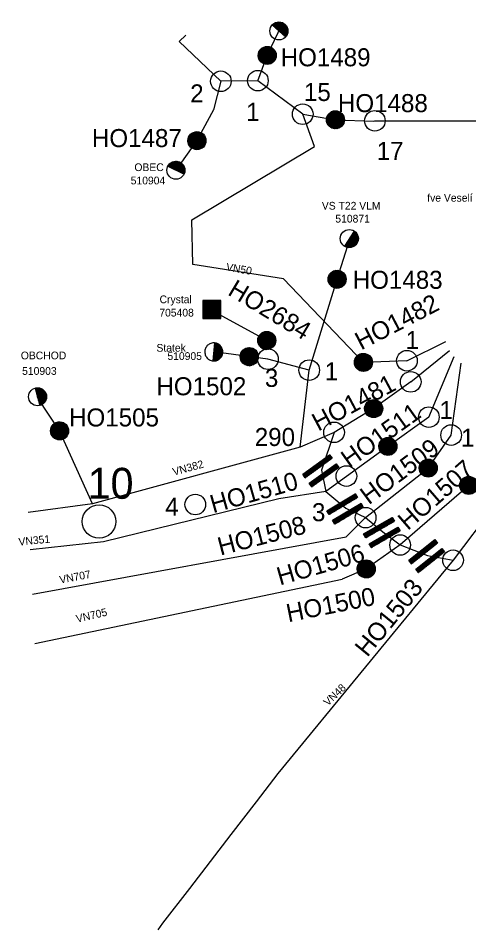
# Model space of a CAD drawing. Extents: x -546092 to -542700, y -1196659 to -1193917.
# Drawn here: x -546092 to -545218, y -1195969 to -1194201 of the extents above; entities that cross this region are included whole.
import ezdxf

# ---------------------------------------------------------------- set-up
doc = ezdxf.new("R2010")
doc.units = 0
for name, color, linetype in [('Default', 7, 'Continuous'), ('Vrstva 1', 7, 'Continuous'), ('Vrstva 2', 7, 'Continuous'), ('Vrstva 3', 7, 'Continuous'), ('Vrstva 5', 7, 'Continuous')]:
    doc.layers.add(name, color=color, linetype=linetype)

# ---------------------------------------------------------------- blocks, each defined once
blk = doc.blocks.new('PS100')
at = {"layer": 'Default'}
for p, q in [((-17.5, -0.7), (0.7, 17.5)), ((-17.5, 0.7), (-0.7, 17.5)), ((-17.4, -2), (2, 17.4)), ((-17.3, 2.2), (-2.2, 17.3)), ((-17.2, -3.3), (3.3, 17.2)), ((-17, 4), (-4, 17)), ((-16.9, -4.4), (4.4, 16.9)), ((-16.6, -5.5), (5.5, 16.6)), ((-16.4, 6), (-6, 16.4)), ((-16.2, -6.5), (6.5, 16.2)), ((-15.8, -7.5), (7.5, 15.8)), ((-15.3, -8.4), (8.4, 15.3)), ((-15.2, 8.6), (-8.6, 15.2)), ((-14.8, -9.3), (9.3, 14.8)), ((-14.2, -10.2), (10.2, 14.2)), ((-13.6, -11), (11, 13.6)), ((-13, -11.7), (11.7, 13)), ((-12.3, -12.5), (12.5, 12.3)), ((-11.5, -13.2), (13.2, 11.5)), ((-10.8, -13.8), (13.8, 10.8)), ((-9.9, -14.4), (14.4, 9.9)), ((-9.1, -14.9), (14.9, 9.1)), ((-8.2, -15.5), (15.5, 8.2)), ((-7.2, -15.9), (15.9, 7.2)), ((-6.2, -16.3), (16.3, 6.2)), ((-5.2, -16.7), (16.7, 5.2)), ((-4.1, -17), (17, 4.1)), ((-2.9, -17.2), (17.2, 2.9)), ((-1.6, -17.4), (17.4, 1.6)), ((-0.3, -17.5), (17.5, 0.3)), ((1.1, -17.4), (17.4, -1.1)), ((2.7, -17.3), (17.3, -2.7)), ((4.5, -16.9), (16.9, -4.5)), ((6.7, -16.2), (16.2, -6.7)), ((9.7, -14.5), (14.5, -9.7))]:
    blk.add_line(p, q, dxfattribs=at)
blk.add_circle((0, 0), 17.5, dxfattribs=at)
blk = doc.blocks.new('PS140')
at = {"layer": 'Default'}
for p, q in [((-17.5, 0), (0, 17.5)), ((-17.4, -1.4), (1.4, 17.4)), ((-17.4, 1.5), (-1.5, 17.4)), ((-17.3, -2.6), (2.6, 17.3)), ((-17.2, 3.1), (-3.1, 17.2)), ((-17.1, -3.8), (3.8, 17.1)), ((-16.8, -4.9), (4.9, 16.8)), ((-16.8, 5), (-5, 16.8)), ((-16.4, -6), (6, 16.4)), ((-16, -7), (7, 16)), ((-15.9, 7.2), (-7.2, 15.9)), ((-15.6, -8), (8, 15.6)), ((-15.1, -8.9), (8.9, 15.1)), ((-14.5, -9.8), (9.8, 14.5)), ((-13.9, -10.6), (10.6, 13.9)), ((-13.8, 10.8), (-10.8, 13.8)), ((-13.3, -11.4), (11.4, 13.3)), ((-12.6, -12.1), (12.1, 12.6)), ((-11.9, -12.8), (12.8, 11.9)), ((-11.2, -13.5), (13.5, 11.2)), ((-10.4, -14.1), (14.1, 10.4)), ((-9.5, -14.7), (14.7, 9.5)), ((-8.6, -15.2), (15.2, 8.6)), ((-7.7, -15.7), (15.7, 7.7)), ((-6.7, -16.1), (16.1, 6.7)), ((-5.7, -16.5), (16.5, 5.7)), ((-4.6, -16.9), (16.9, 4.6)), ((-3.5, -17.1), (17.1, 3.5)), ((-2.3, -17.3), (17.3, 2.3)), ((-1, -17.5), (17.5, 1)), ((0.4, -17.5), (17.5, -0.4)), ((1.9, -17.4), (17.4, -1.9)), ((3.6, -17.1), (17.1, -3.6)), ((5.5, -16.6), (16.6, -5.5)), ((8, -15.6), (15.6, -8))]:
    blk.add_line(p, q, dxfattribs=at)
blk.add_circle((0, 0), 17.5, dxfattribs=at)
blk = doc.blocks.new('PS150')
at = {"layer": 'Default'}
for p, q in [((-15.1, 22.4), (-7.4, 30.1)), ((-15.1, 23.8), (-8.8, 30.1)), ((-15.1, 25.2), (-10.2, 30.1)), ((-15.1, 26.6), (-11.6, 30.1)), ((-15.1, 28), (-13, 30.1)), ((-15.1, 29.4), (-14.4, 30.1)), ((-15.1, 20.9), (-6.5, 29.5)), ((-15.1, 19.5), (-6.5, 28.1)), ((-15.1, 18.1), (-6.5, 26.7)), ((-15.1, 16.7), (-6.5, 25.3)), ((-15.1, 15.3), (-6.5, 23.9)), ((-15.1, 13.9), (-6.5, 22.4)), ((-15.1, 12.5), (-6.5, 21)), ((-15.1, 11), (-6.5, 19.6)), ((-15.1, 9.6), (-6.5, 18.2)), ((6.7, 22.6), (14.1, 30.1)), ((6.7, 24), (12.7, 30.1)), ((6.7, 25.4), (11.3, 30.1)), ((6.7, 26.8), (9.9, 30.1)), ((6.7, 28.3), (8.5, 30.1)), ((6.7, 29.7), (7, 30.1)), ((6.7, 21.2), (15.2, 29.8)), ((6.7, 19.8), (15.2, 28.3)), ((6.7, 18.4), (15.2, 26.9)), ((6.7, 16.9), (15.2, 25.5)), ((6.7, 15.5), (15.2, 24.1)), ((6.7, 14.1), (15.2, 22.7)), ((6.7, 12.7), (15.2, 21.3)), ((6.7, 11.3), (15.2, 19.9)), ((6.7, 9.9), (15.2, 18.4)), ((-15.1, 8.2), (-6.5, 16.8)), ((-15.1, 6.8), (-6.5, 15.4)), ((-15.1, 5.4), (-6.5, 14)), ((-15.1, 4), (-6.5, 12.5)), ((-15.1, 2.6), (-6.5, 11.1)), ((-15.1, 1.2), (-6.5, 9.7)), ((-15.1, -0.3), (-6.5, 8.3)), ((-15.1, -1.7), (-6.5, 6.9)), ((-15.1, -3.1), (-6.5, 5.5)), ((-15.1, -4.5), (-6.5, 4.1)), ((-15.1, -5.9), (-6.5, 2.6)), ((-15.1, -7.3), (-6.5, 1.2)), ((6.7, 8.5), (15.2, 17)), ((6.7, 7.1), (15.2, 15.6)), ((6.7, 5.6), (15.2, 14.2)), ((6.7, 4.2), (15.2, 12.8)), ((6.7, 2.8), (15.2, 11.4)), ((6.7, 1.4), (15.2, 10)), ((6.7, 0), (15.2, 8.5)), ((6.7, -1.4), (15.2, 7.1)), ((6.7, -2.8), (15.2, 5.7)), ((6.7, -4.3), (15.2, 4.3)), ((6.7, -5.7), (15.2, 2.9)), ((6.7, -7.1), (15.2, 1.5)), ((6.7, -8.5), (15.2, 0.1)), ((-15.1, -8.7), (-6.5, -0.2)), ((-15.1, -10.2), (-6.5, -1.6)), ((-15.1, -11.6), (-6.5, -3)), ((-15.1, -13), (-6.5, -4.4)), ((-15.1, -14.4), (-6.5, -5.8)), ((-15.1, -15.8), (-6.5, -7.3)), ((-15.1, -17.2), (-6.5, -8.7)), ((-15.1, -18.6), (-6.5, -10.1)), ((-15.1, -20.1), (-6.5, -11.5)), ((-15.1, -21.5), (-6.5, -12.9)), ((-15.1, -22.9), (-6.5, -14.3)), ((-15.1, -24.3), (-6.5, -15.7)), ((-15.1, -25.7), (-6.5, -17.2)), ((6.7, -9.9), (15.2, -1.4)), ((6.7, -11.3), (15.2, -2.8)), ((6.7, -12.7), (15.2, -4.2)), ((6.7, -14.2), (15.2, -5.6)), ((6.7, -15.6), (15.2, -7)), ((6.7, -17), (15.2, -8.4)), ((6.7, -18.4), (15.2, -9.8)), ((6.7, -19.8), (15.2, -11.3)), ((6.7, -21.2), (15.2, -12.7)), ((6.7, -22.6), (15.2, -14.1)), ((6.7, -24.1), (15.2, -15.5)), ((6.7, -25.5), (15.2, -16.9)), ((-15.1, -27.1), (-6.5, -18.6)), ((-15.1, -28.5), (-6.5, -20)), ((-15.1, -30), (-6.5, -21.4)), ((-15.1, -31.4), (-6.5, -22.8)), ((-15.1, -32.8), (-6.5, -24.2)), ((-15, -34.2), (-6.5, -25.6)), ((-13.6, -34.2), (-6.5, -27.1)), ((-12.2, -34.2), (-6.5, -28.5)), ((-10.8, -34.2), (-6.5, -29.9)), ((-9.4, -34.2), (-6.5, -31.3)), ((-8, -34.2), (-6.5, -32.7)), ((-6.5, -34.2), (-6.5, -34.1)), ((6.7, -26.9), (15.2, -18.3)), ((6.7, -28.3), (15.2, -19.7)), ((6.7, -29.7), (15.2, -21.2)), ((6.7, -31.1), (15.2, -22.6)), ((6.7, -32.5), (15.2, -24)), ((6.7, -34), (15.2, -25.4)), ((7.9, -34.2), (15.2, -26.8)), ((9.3, -34.2), (15.2, -28.2)), ((10.7, -34.2), (15.2, -29.6)), ((12.1, -34.2), (15.2, -31)), ((13.5, -34.2), (15.2, -32.5)), ((14.9, -34.2), (15.2, -33.9))]:
    blk.add_line(p, q, dxfattribs=at)
for points in [[(-6.5, 30.1), (-6.5, -34.2), (-15.1, -34.2), (-15.1, 30.1)], [(15.2, 30.1), (15.2, -34.2), (6.7, -34.2), (6.7, 30.1)]]:
    blk.add_lwpolyline(points, close=True, dxfattribs=at)
blk = doc.blocks.new('PS820')
at = {"layer": 'Vrstva 2'}
blk.add_circle((0, 0), 32.5, dxfattribs=at)
blk = doc.blocks.new('PS610')
at = {"layer": 'Default'}
for p, q in [((0, 16.2), (1.3, 17.4)), ((0, 14.7), (2.5, 17.3)), ((0, 13.3), (3.7, 17.1)), ((0, 11.9), (4.9, 16.8)), ((0, 10.5), (5.9, 16.4)), ((0, 9.1), (7, 16)), ((0, 7.7), (7.9, 15.6)), ((0, 6.3), (8.8, 15.1)), ((0, 4.8), (9.7, 14.5)), ((0, 3.4), (10.5, 14)), ((0, 2), (11.3, 13.3)), ((0, 0.6), (12, 12.7)), ((0, -0.8), (12.8, 12)), ((0, -2.2), (13.4, 11.2)), ((0, -3.6), (14, 10.4)), ((0, -5), (14.6, 9.6)), ((0, -6.5), (15.2, 8.7)), ((0, -7.9), (15.6, 7.8)), ((0, -9.3), (16.1, 6.8)), ((0, -10.7), (16.5, 5.8)), ((0, -12.1), (16.8, 4.7)), ((0, -13.5), (17.1, 3.6)), ((0, -14.9), (17.3, 2.4)), ((0, -16.4), (17.4, 1.1)), ((0.3, -17.5), (17.5, -0.3)), ((1.8, -17.4), (17.4, -1.8)), ((3.5, -17.1), (17.1, -3.5)), ((5.4, -16.7), (16.7, -5.4)), ((7.8, -15.7), (15.6, -7.8))]:
    blk.add_line(p, q, dxfattribs=at)
blk.add_lwpolyline([(0, 17.5), (0, -17.5)], dxfattribs=at)
blk.add_circle((0, 0), 17.5, dxfattribs=at)
blk = doc.blocks.new('PS800')
at = {"layer": 'Vrstva 2'}
blk.add_circle((0, 0), 20, dxfattribs=at)
blk = doc.blocks.new('PS611')
at = {"layer": 'Default'}
for p, q in [((0, 16.2), (1.3, 17.4)), ((0, 14.7), (2.5, 17.3)), ((0, 13.3), (3.7, 17.1)), ((0, 11.9), (4.9, 16.8)), ((0, 10.5), (5.9, 16.4)), ((0, 9.1), (7, 16)), ((0, 7.7), (7.9, 15.6)), ((0, 6.3), (8.8, 15.1)), ((0, 4.8), (9.7, 14.5)), ((0, 3.4), (10.5, 14)), ((0, 2), (11.3, 13.3)), ((0, 0.6), (12, 12.7)), ((0, -0.8), (12.8, 12)), ((0, -2.2), (13.4, 11.2)), ((0, -3.6), (14, 10.4)), ((0, -5), (14.6, 9.6)), ((0, -6.5), (15.2, 8.7)), ((0, -7.9), (15.6, 7.8)), ((0, -9.3), (16.1, 6.8)), ((0, -10.7), (16.5, 5.8)), ((0, -12.1), (16.8, 4.7)), ((0, -13.5), (17.1, 3.6)), ((0, -14.9), (17.3, 2.4)), ((0, -16.4), (17.4, 1.1)), ((0.3, -17.5), (17.5, -0.3)), ((1.8, -17.4), (17.4, -1.8)), ((3.5, -17.1), (17.1, -3.5)), ((5.4, -16.7), (16.7, -5.4)), ((7.8, -15.7), (15.6, -7.8))]:
    blk.add_line(p, q, dxfattribs=at)
for points in [[(17.5, 0), (17.4, 1.8), (17.1, 3.6), (16.6, 5.4), (16, 7.1), (15.2, 8.8), (14.2, 10.3), (13, 11.7), (11.7, 13), (10.3, 14.2), (8.7, 15.2), (7.1, 16), (5.4, 16.6), (3.6, 17.1), (1.8, 17.4), (0, 17.5), (-1.8, 17.4), (-3.6, 17.1), (-5.4, 16.6), (-7.1, 16), (-8.8, 15.2), (-10.3, 14.2), (-11.7, 13), (-13, 11.7), (-14.2, 10.3), (-15.2, 8.7), (-16, 7.1), (-16.6, 5.4), (-17.1, 3.6), (-17.4, 1.8), (-17.5, 0), (-17.4, -1.8), (-17.1, -3.6), (-16.6, -5.4), (-16, -7.1), (-15.2, -8.8), (-14.2, -10.3), (-13, -11.7), (-11.7, -13), (-10.3, -14.2), (-8.8, -15.2), (-7.1, -16), (-5.4, -16.6), (-3.6, -17.1), (-1.8, -17.4), (0, -17.5), (1.8, -17.4), (3.6, -17.1), (5.4, -16.6), (7.1, -16), (8.8, -15.2), (10.3, -14.2), (11.7, -13), (13, -11.7), (14.2, -10.3), (15.2, -8.8), (16, -7.1), (16.6, -5.4), (17.1, -3.6), (17.4, -1.8), (17.5, 0)], [(0, 17.5), (0, -17.5)]]:
    blk.add_lwpolyline(points, dxfattribs=at)
blk = doc.blocks.new('PS631')
at = {"layer": 'Default'}
for p, q in [((-16.6, -14.9), (17.1, 18.7)), ((-16.6, -13.5), (15.7, 18.7)), ((-16.6, -12.1), (14.2, 18.7)), ((-16.6, -10.7), (12.8, 18.7)), ((-16.6, -9.3), (11.4, 18.7)), ((-16.6, -7.9), (10, 18.7)), ((-16.6, -6.5), (8.6, 18.7)), ((-16.6, -5), (7.2, 18.7)), ((-16.6, -3.6), (5.8, 18.7)), ((-16.6, -2.2), (4.3, 18.7)), ((-16.6, -0.8), (2.9, 18.7)), ((-16.6, 0.6), (1.5, 18.7)), ((-16.6, 2), (0.1, 18.7)), ((-16.6, 3.4), (-1.3, 18.7)), ((-16.6, 4.9), (-2.7, 18.7)), ((-16.6, 6.3), (-4.1, 18.7)), ((-16.6, 7.7), (-5.6, 18.7)), ((-16.6, 9.1), (-7, 18.7)), ((-16.6, 10.5), (-8.4, 18.7)), ((-16.6, 11.9), (-9.8, 18.7)), ((-16.6, 13.3), (-11.2, 18.7)), ((-16.6, 14.8), (-12.6, 18.7)), ((-16.6, 16.2), (-14, 18.7)), ((-16.6, 17.6), (-15.5, 18.7)), ((-16.5, -16.3), (18.4, 18.6)), ((-15.1, -16.3), (18.4, 17.2)), ((-13.7, -16.3), (18.4, 15.8)), ((-12.3, -16.3), (18.4, 14.4)), ((-10.9, -16.3), (18.4, 13)), ((-9.4, -16.3), (18.4, 11.6)), ((-8, -16.3), (18.4, 10.2)), ((-6.6, -16.3), (18.4, 8.7)), ((-5.2, -16.3), (18.4, 7.3)), ((-3.8, -16.3), (18.4, 5.9)), ((-2.4, -16.3), (18.4, 4.5)), ((-1, -16.3), (18.4, 3.1)), ((0.5, -16.3), (18.4, 1.7)), ((1.9, -16.3), (18.4, 0.3)), ((3.3, -16.3), (18.4, -1.2)), ((4.7, -16.3), (18.4, -2.6)), ((6.1, -16.3), (18.4, -4)), ((7.5, -16.3), (18.4, -5.4)), ((8.9, -16.3), (18.4, -6.8)), ((10.4, -16.3), (18.4, -8.2)), ((11.8, -16.3), (18.4, -9.6)), ((13.2, -16.3), (18.4, -11.1)), ((14.6, -16.3), (18.4, -12.5)), ((16, -16.3), (18.4, -13.9)), ((17.4, -16.3), (18.4, -15.3))]:
    blk.add_line(p, q, dxfattribs=at)
for points in [[(-16.6, 18.7), (-16.6, -16.3)], [(18.4, 18.7), (-16.6, 18.7)], [(-16.6, 18.7), (-16.6, -16.3)], [(18.4, -16.3), (18.4, 18.7)], [(-16.6, -16.3), (18.4, -16.3)]]:
    blk.add_lwpolyline(points, dxfattribs=at)

msp = doc.modelspace()

# ---------------------------------------------------------------- linework, layer by layer
at = {"layer": 'Vrstva 1'}
for points in [[(-545698.6, -1194323.4), (-545698.6, -1194323.4), (-545779.5, -1194246.2), (-545766.3, -1194234.2)], [(-545608.7, -1194273.3), (-545608.7, -1194273.3), (-545587.8, -1194229), (-545586.2, -1194225.8)], [(-545626.9, -1194322.2), (-545608.7, -1194273.3), (-545608.7, -1194273.3)], [(-545698.6, -1194323.4), (-545698.6, -1194323.4), (-545712.8, -1194378.8), (-545733.5, -1194416.9), (-545745, -1194438.5)], [(-545626.9, -1194322.2), (-545698.6, -1194323.4), (-545698.6, -1194323.4)], [(-545539.9, -1194387.2), (-545626.9, -1194322.3), (-545626.9, -1194322.2)], [(-545422.3, -1194868.4), (-545577.4, -1194706.5), (-545753.3, -1194678.4), (-545755.2, -1194592), (-545517.1, -1194450), (-545539.9, -1194387.2)], [(-545539.9, -1194387.2), (-545476.5, -1194398.1)], [(-545476.5, -1194398.1), (-545476.5, -1194398.1), (-545402.3, -1194400.6), (-545400, -1194400)], [(-545400, -1194400), (-545350, -1194400)], [(-545350, -1194400), (-545300, -1194400)], [(-545300, -1194400), (-545254.4, -1194400)], [(-545254.4, -1194400), (-545253.6, -1194400)], [(-545253.6, -1194400), (-545250, -1194400)], [(-545250, -1194400), (-545100, -1194400)], [(-545745, -1194438.5), (-545785.8, -1194495.8)], [(-545473.3, -1194707.2), (-545448.6, -1194629.4), (-545449.6, -1194628.4)], [(-545527.4, -1194883.5), (-545473.3, -1194707.2)], [(-545609.7, -1194825.8), (-545717.2, -1194766.9)], [(-545337.9, -1194865.2), (-545262.2, -1194828.2)], [(-545607.4, -1194862.2), (-545712.4, -1194848.1)], [(-545330.5, -1194906.2), (-545255.5, -1194845.6)], [(-545295.3, -1194974.6), (-545246.1, -1194857)], [(-545527.4, -1194883.5), (-545607.4, -1194862.2)], [(-545337.9, -1194865.2), (-545422.3, -1194868.4)], [(-545252.1, -1195009.4), (-545232.9, -1194869.8)], [(-545544.9, -1195032.9), (-545527.4, -1194883.5)], [(-545330.5, -1194906.2), (-545402.4, -1194958.1)], [(-546011.3, -1195001.3), (-546011.3, -1195001.3), (-546052.7, -1194938.3), (-546054, -1194935.1)], [(-545402.4, -1194958.1), (-545479.2, -1195004.1)], [(-545295.3, -1194974.6), (-545374.7, -1195031.5)], [(-545947.4, -1195143), (-546011.3, -1195001.3)], [(-545479.2, -1195004.1), (-545544.9, -1195032.9)], [(-545479.2, -1195004.1), (-545503.4, -1195077.3)], [(-545296.5, -1195073.5), (-545252.1, -1195009.4)], [(-545544.9, -1195032.9), (-545947.4, -1195143)], [(-545374.7, -1195031.5), (-545495.3, -1195118.5), (-545495.3, -1195118.6)], [(-545418, -1195169.5), (-545296.5, -1195073.5)], [(-545503.4, -1195077.3), (-545495.3, -1195118.5), (-545495.3, -1195118.6)], [(-545218, -1195106.9), (-545351, -1195222.5)], [(-545495.3, -1195118.6), (-545586.2, -1195132.9)], [(-545495.3, -1195118.6), (-545495.3, -1195118.5), (-545456.1, -1195151.4)], [(-545947.4, -1195143), (-546072.1, -1195159.3)], [(-545586.2, -1195132.9), (-545926.5, -1195216.2), (-546068.4, -1195232.1)], [(-545456.1, -1195151.4), (-545418, -1195169.5)], [(-545169.7, -1195148.3), (-545248.5, -1195252.1)], [(-545455.5, -1195206.5), (-545418, -1195169.5)], [(-545418, -1195169.5), (-545384.8, -1195197.1)], [(-545384.8, -1195197.1), (-545351, -1195222.5)], [(-546064.1, -1195317.8), (-545455.5, -1195206.5)], [(-545351, -1195222.5), (-545416.7, -1195269)], [(-545351, -1195222.5), (-545297.9, -1195242.7)], [(-545297.9, -1195242.7), (-545248.5, -1195252.1)], [(-545248.5, -1195252.1), (-545588.4, -1195665.5), (-545630.5, -1195720.4), (-545679.5, -1195784.1), (-545759.7, -1195888.6), (-545811.5, -1195956.1), (-545821.1, -1195968.6)], [(-545416.7, -1195269), (-545463.4, -1195288.7)], [(-546059.3, -1195413.2), (-545463.4, -1195288.7)]]:
    msp.add_lwpolyline(points, dxfattribs=at)

# ---------------------------------------------------------------- block references
at = {"layer": 'Vrstva 2'}
for name, p, rotation in [('PS140', (-545608.7, -1194273.3), 69.38075276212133), ('PS100', (-545476.5, -1194398.1), 4.474308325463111), ('PS140', (-545745, -1194438.5), 53.94403337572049), ('PS140', (-545473.3, -1194707.2), -32.74128336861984), ('PS100', (-545609.7, -1194825.8), -79.12987295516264), ('PS140', (-545643.5, -1194857.3), -4.957824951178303), ('PS140', (-545422.3, -1194868.4), 12.978016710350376), ('PS140', (-545402.4, -1194958.1), 36.596111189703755), ('PS140', (-546011.3, -1195001.3), 124.90991386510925), ('PS140', (-545374.7, -1195031.5), 34.89601673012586), ('PS150', (-545503.4, -1195077.3), -54.047736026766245), ('PS140', (-545296.5, -1195073.5), 35.223016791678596), ('PS140', (-545218, -1195106.9), 34.7114083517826), ('PS150', (-545456.1, -1195151.4), -59.175191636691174), ('PS150', (-545384.8, -1195197.1), -59.965597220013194), ('PS150', (-545297.9, -1195242.7), -51.5294444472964), ('PS140', (-545416.7, -1195269), 29.886983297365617)]:
    msp.add_blockref(name, p, dxfattribs=dict(at, rotation=rotation))
at = {"layer": 'Vrstva 3'}
for name, p, rotation in [('PS610', (-545586.2, -1194225.8), 48.57538342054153), ('PS610', (-545785.8, -1194495.8), 63.55953053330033), ('PS610', (-545449.6, -1194628.4), -32.74128336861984), ('PS611', (-545712.4, -1194848.1), -5.00033348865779), ('PS610', (-546054, -1194935.1), 14.737852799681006)]:
    msp.add_blockref(name, p, dxfattribs=dict(at, rotation=rotation))
msp.add_blockref('PS631', (-545717.2, -1194766.9), dxfattribs=at)
at = {"layer": 'Vrstva 5'}
for name, p, rotation in [('PS800', (-545698.6, -1194323.4), -51.177683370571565), ('PS800', (-545626.9, -1194322.2), 48.575383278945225), ('PS800', (-545539.9, -1194387.2), -33.77691113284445), ('PS800', (-545400, -1194400), 4.4743081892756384), ('PS800', (-545607.4, -1194862.2), 4.498162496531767), ('PS800', (-545337.9, -1194865.2), -3.7447972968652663), ('PS800', (-545527.4, -1194883.5), -60.76239996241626), ('PS800', (-545330.5, -1194906.2), -155.62636664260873), ('PS800', (-545295.3, -1194974.6), 35.95226383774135), ('PS800', (-545479.2, -1195004.1), 35.95226383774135), ('PS800', (-545252.1, -1195009.4), 32.53439718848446), ('PS800', (-545455.2, -1195088.9), 35.95226383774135), ('PS800', (-545748.2, -1195144.1), 35.95226383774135), ('PS820', (-545934.8, -1195177), 14.738525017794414), ('PS800', (-545418, -1195169.5), 125.22301664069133), ('PS800', (-545351, -1195222.5), 124.71140827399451), ('PS800', (-545248.5, -1195252.1), -34.984636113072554)]:
    msp.add_blockref(name, p, dxfattribs=dict(at, rotation=rotation))

# ---------------------------------------------------------------- texts
at = {"layer": 'Vrstva 1'}
for s, rotation, p in [('VN50', 350.104, (-545689.4, -1194690.2)), ('VN382', 15.301, (-545789.9, -1195088.2)), ('VN351', 5.541, (-546090.2, -1195223.8)), ('VN707', 10.599, (-546010.2, -1195297.4)), ('VN705', 13.128, (-545977.6, -1195373.2)), ('VN48', 44.008, (-545490.9, -1195535.8))]:
    msp.add_text(s, height=15, rotation=rotation, dxfattribs=at).set_placement(p)
at = {"layer": 'Vrstva 2'}
for s, p in [('HO1489', (-545582.7, -1194294.3)), ('HO1488', (-545471.7, -1194383.2)), ('HO1487', (-545948.7, -1194451)), ('HO1483', (-545443, -1194725.8)), ('HO1502', (-545823.6, -1194932.2)), ('HO1505', (-545993, -1194992.7))]:
    msp.add_text(s, height=35, dxfattribs=at).set_placement(p)
for s, rotation, p in [('HO2684', 328.884, (-545687.3, -1194736.2)), ('HO1482', 27.346, (-545426.9, -1194845.4)), ('HO1481', 28.106, (-545509.9, -1195002.8)), ('HO1511', 35.487, (-545449.6, -1195074.5)), ('HO1509', 36.509, (-545411.9, -1195145.6)), ('HO1507', 41.009, (-545336.3, -1195195.6)), ('HO1510', 15.83, (-545713.8, -1195161)), ('HO1508', 14.603, (-545699.6, -1195243.2)), ('HO1506', 16.047, (-545584.3, -1195301.1)), ('HO1503', 50.845, (-545414.7, -1195441.5)), ('HO1500', 11.31, (-545568, -1195372.4))]:
    msp.add_text(s, height=35, rotation=rotation, dxfattribs=at).set_placement(p)
at = {"layer": 'Vrstva 3'}
for s, p in [('OBEC', (-545866.3, -1194497.5)), ('510904', (-545873.5, -1194523.3)), ('fve Veselí n.Moravou Železárny 1', (-545298.5, -1194556.8)), ('VS T22 VLM', (-545502.8, -1194572.2)), ('510871', (-545476.7, -1194597.3)), ('Crystal', (-545817.5, -1194753.7)), ('705408', (-545818, -1194779.5)), ('Statek', (-545823.5, -1194847.7)), ('OBCHOD', (-546086.5, -1194862.5)), ('510905', (-545802.3, -1194863.7)), ('510903', (-546084, -1194892.6))]:
    msp.add_text(s, height=15, dxfattribs=at).set_placement(p)
at = {"layer": 'Vrstva 5'}
for s, height, p in [('2', 35, (-545758.1, -1194364.4)), ('15', 35, (-545537.6, -1194361.6)), ('1', 35, (-545649.7, -1194400.1)), ('17', 35, (-545396.5, -1194475.8)), ('1', 35, (-545340.4, -1194842.6)), ('1', 35, (-545497.2, -1194903.4)), ('3', 35, (-545613.3, -1194916)), ('1', 35, (-545274.8, -1194978.4)), ('290', 35, (-545632.9, -1195030.6)), ('1', 35, (-545233.1, -1195032)), ('10', 60, (-545957.2, -1195132.9)), ('4', 35, (-545806.5, -1195165.7)), ('3', 35, (-545522, -1195176.4))]:
    msp.add_text(s, height=height, dxfattribs=at).set_placement(p)

doc.saveas('drawing.dxf')
